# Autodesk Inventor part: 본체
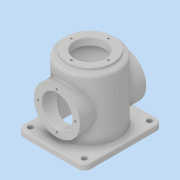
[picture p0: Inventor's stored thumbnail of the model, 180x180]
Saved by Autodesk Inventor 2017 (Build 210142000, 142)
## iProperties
Part Number: 본체
Material: 일반
Document SubType Name: Modeling
Designer: MRC
Density: 1 g/cm^3
Appearance: 기본값
Author: MRC
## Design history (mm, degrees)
sketch "스케치1"
  geometry: C1 r 50 at (0, 0); 1 further point
  constraints: 1 centre point, 1 coincident
  dimensions: "d0" = 100 diameter of C1
extrude "돌출1" new body sketch "스케치1" stored distance "d1" = 120; taper "d2" = 0 deg
sketch "스케치2"
  geometry: L1 (-60, 70)-(60, 70); L2 (60, 70)-(60, -70); L3 (60, -70)-(-60, -70); L4 (-60, -70)-(-60, 70); L5 (-60, 70)-(60, -70); L6 (60, 70)-(-60, -70); C1 r 50 at (0, 0) reference
  constraints: 12 end point, 2 midpoint, 2 parallel, 1 horizontal, 1 perpendicular
  dimensions: "d3" = 120 distance of L2.end L3.end; "d4" = 140 distance of L1.end L2.end
extrude "돌출2" join sketch "스케치2" distance "d5" = 10; taper "d6" = 0 deg
sketch "스케치3"
  geometry: C1 r 50 at (0, 0) reference; C2 r 41 at (0, 0)
  constraints: 1 centre point, 1 coincident
  dimensions: "d7" = 82 diameter of C2
extrude "돌출3" join sketch "스케치3" distance "d8" = 5; taper "d9" = 0 deg
sketch "스케치5"
  geometry: C1 r 41 at (0, 0) reference; C2 r 27 at (0, 0)
  constraints: 1 centre point, 1 coincident
  dimensions: "d13" = 54 diameter of C2
extrude "돌출5" cut sketch "스케치5" distance "d14" = 13; taper "d15" = 0 deg
sketch "스케치6"
  geometry: C1 r 41 at (0, 0); 1 further point
  constraints: 1 centre point, 1 coincident
  dimensions: "d16" = 82 diameter of C1
extrude "돌출6" join sketch "스케치6" stored distance "d17" = 118; taper "d18" = 0 deg
sketch "스케치7"
  geometry: C1 r 41 at (0, 0) reference; C2 r 27 at (0, 0)
  constraints: 1 centre point, 1 coincident
  dimensions: "d19" = 54 diameter of C2
extrude "돌출7" cut sketch "스케치7" stored distance "d20" = 118; taper "d21" = 0 deg
sketch "스케치8"
  geometry: C1 r 27 at (0, 0) reference; 1 further point
  constraints: 1 vertical alignment
  dimensions: "d22" = 33 distance of C1.centre point (0, 33)
hole "구멍1" sketch "스케치8" at (0, 33) diameter "d23" = 3.242; stored, may be unused: countersink angle "d27" = 90 deg, drill point angle "d29" = 118 deg; dims "d24" = 8, "d25" = 4, "d26" = 2, "d28" = 10
sketch "스케치9"
  geometry: C1 r 27 at (0, 0) reference; 1 further point
  constraints: 1 vertical alignment
  dimensions: "d33" = 33 distance of C1.centre point (0, 33)
hole "구멍2" sketch "스케치9" at (0, 33) diameter "d34" = 3.242; stored, may be unused: countersink angle "d38" = 90 deg, drill point angle "d40" = 118 deg; dims "d35" = 8, "d36" = 4, "d37" = 2, "d39" = 10
fillet "모깎기1" dims "d44" = 12
sketch "스케치10"
  geometry: C1 r 4.5 at (-48, 58); A1 r 12 centre (-48, 58) between (-48, 70) and (-60, 58) reference
  constraints: 1 centre point, 1 coincident
  dimensions: "d45" = 9 diameter of C1
extrude "돌출8" cut sketch "스케치10" stored distance "d46" = 118; taper "d47" = 0 deg
fillet "모깎기2" dims "d48" = 3
chamfer "모따기1" distance "d49" = 1; stored, may be unused: second distance "d50" = 2, angle "d51" = 45 deg
chamfer "모따기2" distance "d52" = 1; stored, may be unused: second distance "d53" = 2, angle "d54" = 45 deg
fillet "모깎기3" dims "d55" = 6
fillet "모깎기4" dims "d56" = 3
fillet "모깎기5" dims "d57" = 3
fillet "모깎기6" dims "d58" = 3
sketch "스케치11"
  geometry: C1 r 42 at (0, 0); 1 further point
  constraints: 1 centre point, 1 coincident
  dimensions: "d59" = 84 diameter of C1
extrude "돌출9" cut sketch "스케치11" distance "d60" = 112; taper "d61" = 0 deg
fillet "모깎기7" dims "d62" = 3
node "작업 평면1"
sketch "스케치12"
  geometry: L1 (-60, 58)-(-60, -58) reference; 2 further points
  constraints: 1 horizontal alignment, 1 other
  dimensions: "d64" = 66 distance from line of L1 point (6, 0)
feature "엠보싱1" sketch "스케치12" dims "d1" = 120, "d65" = 0.5, "d66" = 0
node "솔리드1"
pattern_circular "원형 패턴1" dims angle "d31" = 360 deg
mirror "미러1"
pattern_circular "원형 패턴2" dims angle "d42" = 360 deg
mirror "미러2"
mirror "미러3"
other parameters: "d63" = 80.5
